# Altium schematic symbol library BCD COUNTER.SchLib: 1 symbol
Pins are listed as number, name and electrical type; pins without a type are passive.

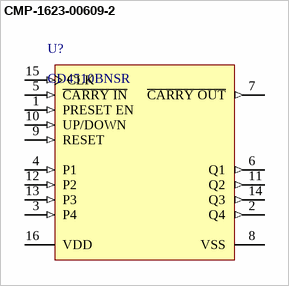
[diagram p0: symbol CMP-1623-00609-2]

## CMP-1623-00609-2
designator U?, comment CD4510BNSR
CMOS Presettable BCD Up/Down Counter, NS0016A, LARGE T&R; Manufacturer: Texas Instruments; Bits(#): 4; VCC(Min)(V): 3; Voltage(Nom)(V): 5,10,15; Schmitt Trigger: No; Output Drive (IOL/IOH)(Max)(mA): 1.5/-1.5; Rating: Catalog; Inputs: 1; VCC(Max)(V): 18; Technology Family: CD4000; F @ Nom Voltage(Max)(Mhz): 8; ICC @ Nom Voltage(Max)(mA): 0.03; tpd @ Nom Voltage(Max)(ns): 200
footprint NS0016A_L (SOIC,16-Leads,Body 10.5x5.6mm,Pitch 1.27mm,IPC High Density)
footprint NS0016A_N (SOIC,16-Leads,Body 10.5x5.6mm,Pitch 1.27mm,IPC Medium Density)
footprint NS0016A_M (SOIC,16-Leads,Body 10.5x5.6mm,Pitch 1.27mm,IPC Low Density)
pins: 1 PRESET EN (in), 2 Q4 (out), 3 P4 (in), 4 P1 (in), 5 ~{CARRY IN} (in), 6 Q1 (out), 7 ~{CARRY OUT} (out), 8 VSS (power), 9 RESET (in), 10 UP/DOWN (in), 11 Q2 (out), 12 P2 (in), 13 P3 (in), 14 Q3 (out), 15 CLK (in), 16 VDD (power)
